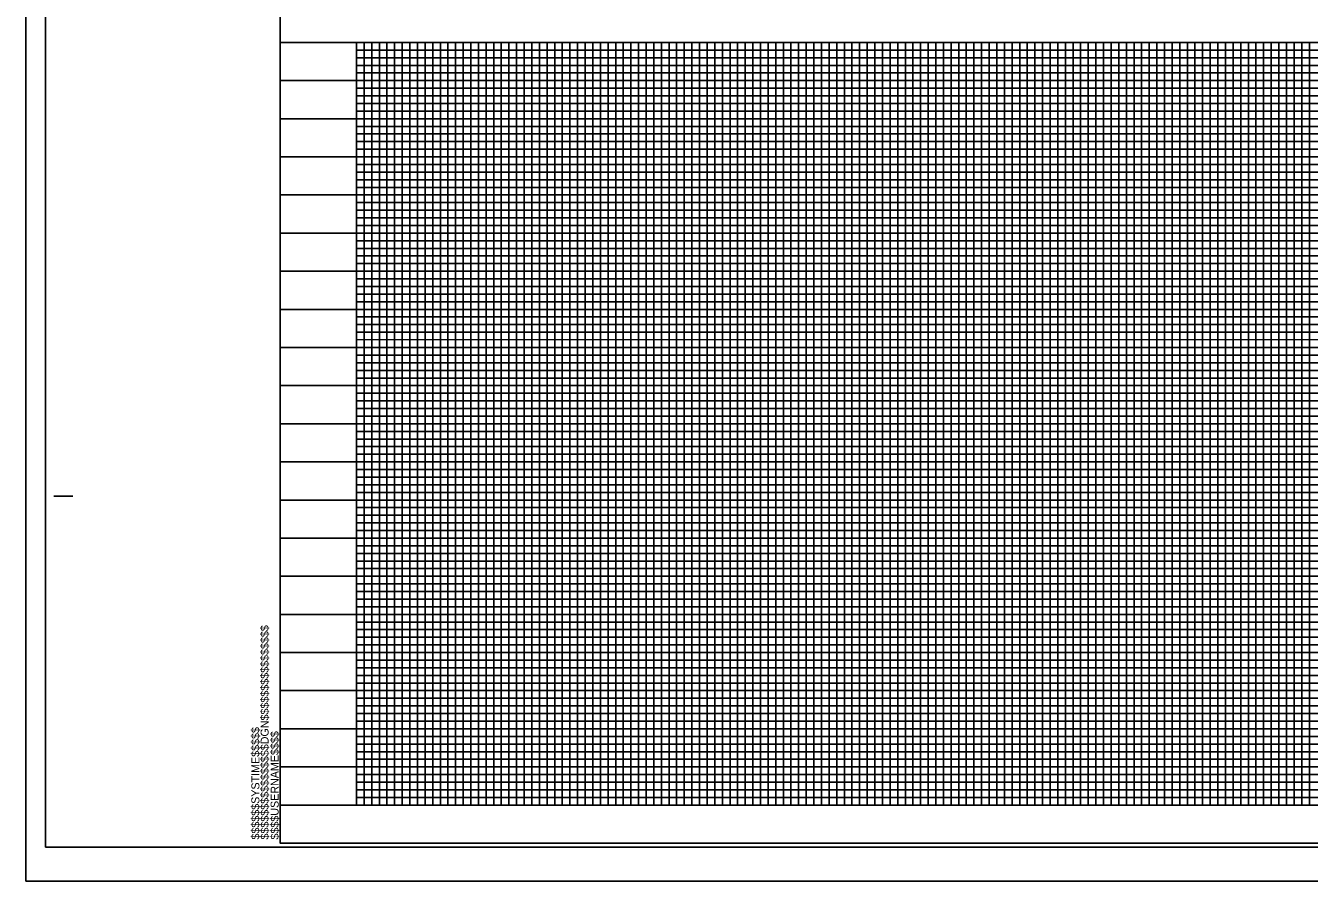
# Model space of a CAD drawing. Extents: x 2356353 to 2358037, y 848519 to 849619.
# Drawn here: x 2356353 to 2357195, y 848519 to 849080 of the extents above; entities that cross this region are included whole.
import ezdxf

# ---------------------------------------------------------------- set-up
doc = ezdxf.new("R2010")
doc.units = 0
for name, color, linetype in [('Default', 7, 'Continuous'), ('Sheet Cutting Line CELL', 7, 'Continuous'), ('Sheet DOT Grid CELL', 7, 'Continuous'), ('Sheet Layout Profile Border Port 2', 7, 'Continuous'), ('Sheet Plot Border Inside CELL', 7, 'Continuous'), ('Sheet Plot Border Outside CELL', 7, 'Continuous'), ('Sheet Profile CELL', 7, 'Continuous'), ('Sheet Profile Grid Major CELL', 7, 'Continuous'), ('Sheet Profile Grid Middle CELL', 7, 'Continuous'), ('Sheet Profile Grid Minor CELL', 7, 'Continuous')]:
    doc.layers.add(name, color=color, linetype=linetype)

msp = doc.modelspace()

# ---------------------------------------------------------------- linework, layer by layer
at = {"layer": 'Default'}
msp.add_lwpolyline([(2356570.19, 849069.44), (2357970.19, 849069.44), (2357970.19, 848569.44), (2356570.19, 848569.44)], close=True, dxfattribs=at)
at = {"layer": 'Sheet Cutting Line CELL'}
for p, q in [((2356353.19, 849619.44), (2356353.19, 848519.44)), ((2356353.19, 848519.44), (2358037.19, 848519.44))]:
    msp.add_line(p, q, dxfattribs=at)
at = {"layer": 'Sheet DOT Grid CELL'}
for p, q in [((2356520.19, 849069.44), (2358020.07, 849069.44)), ((2356570.19, 849069.44), (2356570.19, 848569.44)), ((2356620.19, 849069.44), (2356620.19, 848569.44)), ((2356670.19, 849069.44), (2356670.19, 848569.44)), ((2356720.19, 849069.44), (2356720.19, 848569.44)), ((2356770.19, 849069.44), (2356770.19, 848569.44)), ((2356820.19, 849069.44), (2356820.19, 848569.44)), ((2356870.19, 849069.44), (2356870.19, 848569.44)), ((2356920.19, 849069.44), (2356920.19, 848569.44)), ((2356970.19, 849069.44), (2356970.19, 848569.44)), ((2357020.19, 849069.44), (2357020.19, 848569.44)), ((2357070.19, 849069.44), (2357070.19, 848569.44)), ((2357120.19, 849069.44), (2357120.19, 848569.44)), ((2357170.19, 849069.44), (2357170.19, 848569.44)), ((2356520.19, 849019.44), (2358020.07, 849019.44)), ((2356520.19, 848969.44), (2358020.07, 848969.44)), ((2356520.19, 848919.44), (2358020.07, 848919.44)), ((2356520.19, 848869.44), (2358020.07, 848869.44)), ((2356520.19, 848819.44), (2358020.07, 848819.44)), ((2356520.19, 848769.44), (2358020.07, 848769.44)), ((2356520.19, 848719.44), (2358020.07, 848719.44)), ((2356520.19, 848669.44), (2358020.07, 848669.44)), ((2356520.19, 848619.44), (2358020.07, 848619.44))]:
    msp.add_line(p, q, dxfattribs=at)
at = {"layer": 'Sheet Layout Profile Border Port 2'}
msp.add_lwpolyline([(2356570.19, 849069.44), (2357970.19, 849069.44), (2357970.19, 848569.44), (2356570.19, 848569.44)], close=True, dxfattribs=at)
at = {"layer": 'Sheet Plot Border Inside CELL'}
msp.add_lwpolyline([(2356366.19, 848541.89), (2358032.69, 848541.89), (2358032.69, 849596.99), (2356366.19, 849596.99)], close=True, dxfattribs=at)
at = {"layer": 'Sheet Plot Border Outside CELL'}
msp.add_lwpolyline([(2356353.19, 848519.44), (2358037.19, 848519.44), (2358037.19, 849619.44), (2356353.19, 849619.44)], close=True, dxfattribs=at)
at = {"layer": 'Sheet Profile CELL'}
for p, q in [((2356520.19, 849069.44), (2358020.19, 849069.44)), ((2356371.69, 848771.94), (2356384.19, 848771.94)), ((2358020.19, 848569.44), (2356520.19, 848569.44)), ((2356520.19, 848544.44), (2358020.19, 848544.44)), ((2356520.19, 848544.44), (2356520.19, 848544.44)), ((2356520.19, 848544.44), (2356520.19, 848544.44)), ((2356520.19, 848544.44), (2356520.19, 848544.44)), ((2356520.19, 848544.44), (2356520.19, 848544.44)), ((2356520.19, 848544.44), (2356520.19, 848544.44)), ((2356520.19, 848544.44), (2356520.19, 848544.44)), ((2356520.19, 848544.44), (2356520.19, 848544.44))]:
    msp.add_line(p, q, dxfattribs=at)
msp.add_lwpolyline([(2358020.19, 849594.44), (2356520.19, 849594.44), (2356520.19, 848544.44), (2358020.19, 848544.44)], close=True, dxfattribs=at)
msp.add_lwpolyline([(2356557.69, 848544.44), (2356557.69, 848544.44)], dxfattribs=at)
at = {"layer": 'Sheet Profile Grid Major CELL'}
for p, q in [((2357020.19, 849069.44), (2357070.19, 849069.44)), ((2357120.19, 849069.44), (2357170.19, 849069.44)), ((2356520.19, 848569.44), (2356520.19, 848569.44))]:
    msp.add_line(p, q, dxfattribs=at)
for points in [[(2356570.19, 849069.44), (2356570.19, 848569.44), (2356620.19, 848569.44), (2356620.19, 849069.44), (2356670.19, 849069.44), (2356670.19, 848569.44), (2356720.19, 848569.44), (2356720.19, 849069.44), (2356770.19, 849069.44), (2356770.19, 848569.44), (2356820.19, 848569.44), (2356820.19, 849069.44), (2356870.19, 849069.44), (2356870.19, 848569.44), (2356920.19, 848569.44), (2356920.19, 849069.44), (2356970.19, 849069.44), (2356970.19, 848569.44), (2357020.19, 848569.44), (2357020.19, 849069.44), (2357070.19, 849069.44), (2357070.19, 848569.44), (2357120.19, 848569.44), (2357120.19, 849069.44), (2357170.19, 849069.44), (2357170.19, 848569.44), (2357220.19, 848569.44)], [(2358020.19, 849019.44), (2356520.19, 849019.44)], [(2358020.19, 848969.44), (2356520.19, 848969.44), (2356520.19, 848919.44), (2358020.19, 848919.44)], [(2358020.19, 848869.44), (2356520.19, 848869.44), (2356520.19, 848819.44), (2358020.19, 848819.44)], [(2358020.19, 848769.44), (2356520.19, 848769.44), (2356520.19, 848719.44), (2358020.19, 848719.44)], [(2358020.19, 848669.44), (2356520.19, 848669.44), (2356520.19, 848669.44), (2356520.19, 848619.44), (2358020.19, 848619.44)], [(2358020.19, 848569.44), (2356520.19, 848569.44)]]:
    msp.add_lwpolyline(points, dxfattribs=at)
at = {"layer": 'Sheet Profile Grid Middle CELL'}
for points in [[(2356545.19, 849069.44), (2356595.19, 849069.44), (2356595.19, 848569.44), (2356645.19, 848569.44), (2356645.19, 849069.44), (2356695.19, 849069.44), (2356695.19, 848569.44), (2356745.19, 848569.44), (2356745.19, 849069.44), (2356795.19, 849069.44), (2356795.19, 848569.44), (2356845.19, 848569.44), (2356845.19, 849069.44), (2356895.19, 849069.44), (2356895.19, 848569.44), (2356945.19, 848569.44), (2356945.19, 849069.44), (2356995.19, 849069.44), (2356995.19, 848569.44), (2357045.19, 848569.44), (2357045.19, 849069.44), (2357095.19, 849069.44), (2357095.19, 848569.44), (2357145.19, 848569.44), (2357145.19, 848569.44), (2357145.19, 849069.44), (2357195.19, 849069.44), (2357195.19, 848569.44), (2357245.19, 848569.44)], [(2356520.19, 849044.44), (2358020.19, 849044.44)], [(2358020.19, 848994.44), (2356520.19, 848994.44), (2356520.19, 848944.44), (2358020.19, 848944.44)], [(2358020.19, 848894.44), (2356520.19, 848894.44), (2356520.19, 848844.44), (2358020.19, 848844.44)], [(2358020.19, 848794.44), (2356520.19, 848794.44), (2356520.19, 848744.44), (2358020.19, 848744.44)], [(2358020.19, 848694.44), (2356520.19, 848694.44), (2356520.19, 848644.44), (2358020.19, 848644.44)], [(2358020.19, 848594.44), (2356520.19, 848594.44)]]:
    msp.add_lwpolyline(points, dxfattribs=at)
at = {"layer": 'Sheet Profile Grid Minor CELL'}
for p, q in [((2356570.19, 849064.44), (2357970.19, 849064.44)), ((2357970.19, 849059.44), (2356570.19, 849059.44)), ((2356570.19, 849054.44), (2357970.19, 849054.44)), ((2357970.19, 849049.44), (2356570.19, 849049.44)), ((2356570.19, 849039.44), (2357970.19, 849039.44)), ((2357970.19, 849034.44), (2356570.19, 849034.44)), ((2356570.19, 849029.44), (2357970.19, 849029.44)), ((2357970.19, 849024.44), (2356570.19, 849024.44)), ((2356570.19, 849014.44), (2357970.19, 849014.44)), ((2357970.19, 849009.44), (2356570.19, 849009.44)), ((2356570.19, 849004.44), (2357970.19, 849004.44)), ((2357970.19, 848999.44), (2356570.19, 848999.44)), ((2356570.19, 848989.44), (2357970.19, 848989.44)), ((2357970.19, 848984.44), (2356570.19, 848984.44)), ((2356570.19, 848979.44), (2357970.19, 848979.44)), ((2357970.19, 848974.44), (2356570.19, 848974.44)), ((2356570.19, 848964.44), (2357970.19, 848964.44)), ((2357970.19, 848959.44), (2356570.19, 848959.44)), ((2356570.19, 848954.44), (2357970.19, 848954.44)), ((2357970.19, 848949.44), (2356570.19, 848949.44)), ((2356570.19, 848939.44), (2357970.19, 848939.44)), ((2357970.19, 848934.44), (2356570.19, 848934.44)), ((2356570.19, 848929.44), (2357970.19, 848929.44)), ((2357970.19, 848924.44), (2356570.19, 848924.44)), ((2356570.19, 848914.44), (2357970.19, 848914.44)), ((2357970.19, 848909.44), (2356570.19, 848909.44)), ((2356570.19, 848904.44), (2357970.19, 848904.44)), ((2357970.19, 848899.44), (2356570.19, 848899.44)), ((2356570.19, 848889.44), (2357970.19, 848889.44)), ((2357970.19, 848884.44), (2356570.19, 848884.44)), ((2356570.19, 848879.44), (2357970.19, 848879.44)), ((2357970.19, 848874.44), (2356570.19, 848874.59)), ((2356570.19, 848864.44), (2357970.19, 848864.44)), ((2357970.19, 848859.44), (2356570.19, 848859.44)), ((2356570.19, 848854.44), (2357970.19, 848854.44)), ((2357970.19, 848849.44), (2356570.19, 848849.44)), ((2356570.19, 848839.44), (2357970.19, 848839.44)), ((2357970.19, 848834.44), (2356570.19, 848834.44)), ((2356570.19, 848829.44), (2357970.19, 848829.44)), ((2357970.19, 848824.44), (2356570.19, 848824.44)), ((2356570.19, 848814.44), (2357970.19, 848814.44)), ((2357970.19, 848809.44), (2356570.19, 848809.44)), ((2356570.19, 848804.44), (2357970.19, 848804.44)), ((2357970.19, 848799.44), (2356570.19, 848799.44)), ((2356570.19, 848789.44), (2357970.19, 848789.44)), ((2357970.19, 848784.44), (2356570.19, 848784.44)), ((2356570.19, 848779.44), (2357970.19, 848779.44)), ((2357970.19, 848774.44), (2356570.19, 848774.44)), ((2356570.19, 848764.44), (2357970.19, 848764.44)), ((2357970.19, 848759.44), (2356570.19, 848759.44)), ((2356570.19, 848754.44), (2357970.19, 848754.44)), ((2357970.19, 848749.44), (2356570.19, 848749.44)), ((2356570.19, 848739.44), (2357970.19, 848739.44)), ((2357970.19, 848734.44), (2356570.19, 848734.44)), ((2356570.19, 848729.44), (2357970.19, 848729.44)), ((2357970.19, 848724.44), (2356570.19, 848724.44)), ((2356570.19, 848714.44), (2357970.19, 848714.44)), ((2357970.19, 848709.44), (2356570.19, 848709.44)), ((2356570.19, 848704.44), (2357970.19, 848704.44)), ((2357970.19, 848699.44), (2356570.19, 848699.44)), ((2356570.19, 848689.44), (2357970.19, 848689.44)), ((2357970.19, 848684.44), (2356570.19, 848684.44)), ((2356570.19, 848679.44), (2357970.19, 848679.44)), ((2357970.19, 848674.44), (2356570.19, 848674.44)), ((2356570.19, 848664.44), (2357970.19, 848664.44)), ((2357970.19, 848659.44), (2356570.19, 848659.44)), ((2356570.19, 848654.44), (2357970.19, 848654.44)), ((2357970.19, 848649.44), (2356570.19, 848649.44)), ((2356570.19, 848639.44), (2357970.19, 848639.44)), ((2357970.19, 848634.44), (2356570.19, 848634.44)), ((2356570.19, 848629.44), (2357970.19, 848629.44)), ((2357970.19, 848624.44), (2356570.19, 848624.44)), ((2356570.19, 848614.44), (2357970.19, 848614.44)), ((2357970.19, 848609.44), (2356570.19, 848609.44)), ((2356570.19, 848604.44), (2357970.19, 848604.44)), ((2357970.19, 848599.44), (2356570.19, 848599.44)), ((2356570.19, 848589.44), (2357970.19, 848589.44)), ((2357970.19, 848584.44), (2356570.19, 848584.44)), ((2356570.19, 848579.44), (2357970.19, 848579.44)), ((2356570.19, 848574.44), (2357970.19, 848574.44))]:
    msp.add_line(p, q, dxfattribs=at)
for points in [[(2356570.19, 849069.44), (2356575.19, 849069.44), (2356575.19, 848569.44), (2356580.19, 848569.44), (2356580.19, 849069.44), (2356585.19, 849069.44), (2356585.19, 848569.44), (2356590.19, 848569.44), (2356590.19, 849069.44), (2356600.19, 849069.44), (2356600.19, 848569.44), (2356605.19, 848569.44), (2356605.19, 849069.44), (2356610.19, 849069.44), (2356610.19, 848569.44), (2356615.19, 848569.44), (2356625.19, 848569.44), (2356630.19, 848569.44), (2356630.19, 849069.44), (2356635.19, 849069.44), (2356635.19, 848569.44), (2356640.19, 848569.44), (2356640.19, 849069.44), (2356650.19, 849069.44), (2356650.19, 848569.44), (2356655.19, 848569.44), (2356655.19, 849069.44), (2356660.19, 849069.44), (2356660.19, 848569.44), (2356665.19, 848569.44), (2356665.19, 849069.44), (2356675.19, 849069.44), (2356675.19, 848569.44), (2356680.19, 848569.44), (2356680.19, 849069.44), (2356685.19, 849069.44), (2356685.19, 848569.44), (2356690.19, 848569.44), (2356690.19, 849069.44), (2356700.19, 849069.44), (2356700.19, 848569.44), (2356705.19, 848569.44), (2356705.19, 849069.44), (2356710.19, 849069.44), (2356710.19, 848569.44), (2356715.19, 848569.44), (2356715.19, 849069.44), (2356725.19, 849069.44), (2356725.19, 848569.44), (2356730.19, 848569.44), (2356730.19, 849069.44), (2356735.19, 849069.44), (2356735.19, 848569.44), (2356740.19, 848569.44), (2356740.19, 849069.44), (2356750.19, 849069.44), (2356750.19, 848569.44), (2356755.19, 848569.44), (2356755.19, 849069.44), (2356760.19, 849069.44), (2356760.19, 848569.44), (2356765.19, 848569.44), (2356765.19, 849069.44), (2356775.19, 849069.44), (2356775.19, 848569.44), (2356780.19, 848569.44), (2356780.19, 849069.44), (2356785.19, 849069.44), (2356785.19, 848569.44)], [(2356615.19, 848569.44), (2356615.19, 849069.44), (2356625.19, 849069.44), (2356625.19, 848569.44)], [(2356785.19, 848569.44), (2356790.19, 848569.44), (2356790.19, 849069.44), (2356800.19, 849069.44), (2356800.19, 848569.44), (2356805.19, 848569.44), (2356805.19, 849069.44), (2356810.19, 849069.44), (2356810.19, 848569.44), (2356815.19, 848569.44), (2356815.19, 849069.44), (2356825.19, 849069.44), (2356825.19, 848569.44), (2356830.19, 848569.44), (2356830.19, 849069.44), (2356835.19, 849069.44), (2356835.19, 848569.44), (2356840.19, 848569.44), (2356840.19, 849069.44), (2356850.19, 849069.44), (2356850.19, 848569.44), (2356855.19, 848569.44), (2356855.19, 849069.44), (2356860.19, 849069.44), (2356860.19, 848569.44), (2356865.19, 848569.44), (2356865.19, 849069.44), (2356875.19, 849069.44), (2356875.19, 848569.44), (2356880.19, 848569.44), (2356880.19, 849069.44), (2356885.19, 849069.44), (2356885.19, 848569.44), (2356890.19, 848569.44), (2356890.19, 849069.44), (2356900.19, 849069.44), (2356900.19, 848569.44), (2356905.19, 848569.44), (2356905.19, 849069.44), (2356910.19, 849069.44), (2356910.19, 848569.44), (2356915.19, 848569.44), (2356915.19, 849069.44), (2356925.19, 849069.44), (2356925.19, 848569.44), (2356930.19, 848569.44), (2356930.19, 849069.44), (2356935.19, 849069.44), (2356935.19, 848569.44), (2356940.19, 848569.44), (2356940.19, 849069.44), (2356950.19, 849069.44), (2356950.19, 848569.44), (2356955.19, 848569.44), (2356955.19, 849069.44), (2356960.19, 849069.44), (2356960.19, 848569.44), (2356965.19, 848569.44), (2356965.19, 849069.44), (2356975.19, 849069.44), (2356975.19, 848569.44), (2356980.19, 848569.44), (2356980.19, 849069.44), (2356985.19, 849069.44), (2356985.19, 848569.44), (2356990.19, 848569.44), (2356990.19, 849069.44), (2357000.19, 849069.44), (2357000.19, 848569.44), (2357005.19, 848569.44), (2357005.19, 849069.44), (2357010.19, 849069.44), (2357010.19, 848569.44), (2357015.19, 848569.44), (2357015.19, 849069.44), (2357025.19, 849069.44), (2357025.19, 848569.44), (2357030.19, 848569.44), (2357030.19, 849069.44), (2357035.19, 849069.44), (2357035.19, 848569.44), (2357040.19, 848569.44), (2357040.19, 849069.44), (2357050.19, 849069.44), (2357050.19, 848569.44), (2357055.19, 848569.44), (2357055.19, 849069.44), (2357060.19, 849069.44), (2357060.19, 848569.44), (2357065.19, 848569.44), (2357065.19, 849069.44), (2357075.19, 849069.44), (2357075.19, 848569.44), (2357080.19, 848569.44), (2357080.19, 849069.44), (2357085.19, 849069.44), (2357085.19, 848569.44), (2357090.19, 848569.44), (2357090.19, 849069.44), (2357100.19, 849069.44)], [(2357100.19, 849069.44), (2357100.19, 848569.44), (2357105.19, 848569.44), (2357105.19, 849069.44), (2357110.19, 849069.44), (2357110.19, 848569.44), (2357115.19, 848569.44), (2357115.19, 849069.44), (2357125.19, 849069.44), (2357125.19, 848569.44), (2357130.19, 848569.44), (2357130.19, 849069.44), (2357135.19, 849069.44), (2357135.19, 848569.44), (2357140.19, 848569.44), (2357140.19, 849069.44), (2357150.19, 849069.44), (2357150.19, 848569.44), (2357155.19, 848569.44), (2357155.19, 849069.44), (2357160.19, 849069.44), (2357160.19, 848569.44), (2357165.19, 848569.44), (2357165.19, 849069.44), (2357175.19, 849069.44), (2357175.19, 848569.44), (2357180.19, 848569.44), (2357180.19, 849069.44), (2357185.19, 849069.44), (2357185.19, 848569.44), (2357190.19, 848569.44), (2357190.19, 849069.44), (2357200.19, 849069.44)]]:
    msp.add_lwpolyline(points, dxfattribs=at)

# ---------------------------------------------------------------- texts
at = {"layer": 'Sheet Profile CELL'}
for s, p in [('$$$$$$$$$$$$$$$$DGN$$$$$$$$$$$$$$$$', (2356512.55, 848546.81)), ('$$$$$$SYSTIME$$$$$', (2356506.5, 848546.81)), ('$$$$USERNAME$$$$', (2356519.12, 848546.83))]:
    msp.add_text(s, height=5.25, rotation=90, dxfattribs=at).set_placement(p)

doc.saveas('drawing.dxf')
